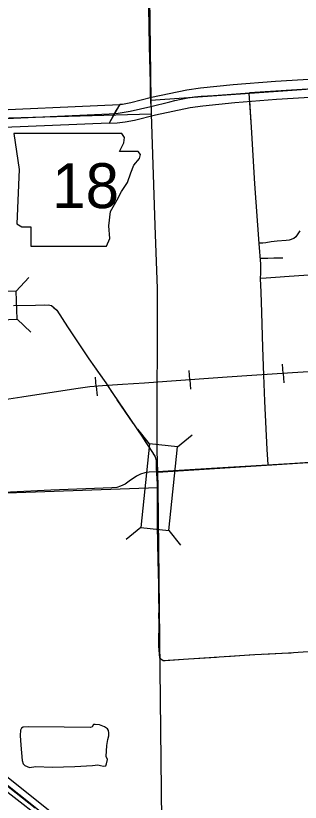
# Model space of a CAD drawing. Extents: x 646058 to 725608, y 1473014 to 1561048.
# Drawn here: x 656968 to 658973, y 1548182 to 1553726 of the extents above; entities that cross this region are included whole.
import ezdxf

# ---------------------------------------------------------------- set-up
doc = ezdxf.new("R2010")
doc.units = 0
doc.layers.add('Default', color=7, linetype='Continuous')

msp = doc.modelspace()

# ---------------------------------------------------------------- linework, layer by layer
at = {"layer": 'Default'}
for p, q in [((656970.4, 1551783.9), (657060, 1551880.9)), ((656978.2, 1551586.1), (657075.2, 1551496.5)), ((658852.6, 1551204.4), (658848.3, 1551270.2)), ((658194.2, 1551158.8), (658189.5, 1551224.6)), ((658852.6, 1551204.4), (658857, 1551138.5)), ((657535.8, 1551113.3), (657530.1, 1551179.1)), ((658194.2, 1551158.8), (658198.9, 1551092.9)), ((657535.8, 1551113.3), (657541.4, 1551047.6)), ((657911.1, 1550709.1), (657828, 1550811.6)), ((658108, 1550688.4), (658210.6, 1550771.5)), ((657849.1, 1550118.3), (657746.5, 1550035.2)), ((658046, 1550097.6), (658129, 1549995.1))]:
    msp.add_line(p, q, dxfattribs=at)
for points in [[(657836.4, 1559731.1), (657852.6, 1558422.3), (657853.7, 1558332.9), (657886.7, 1555776.3), (657888, 1555674.8), (657919.2, 1553129.9), (657922.4, 1553034.6), (657948.9, 1552246.6), (657964.6, 1551804.3), (657962.8, 1550661.1), (657966.7, 1550505.3), (657969.3, 1550400.1), (657996.7, 1547841.2)], [(657882.9, 1555670.5), (657887.5, 1555419.8), (657888.3, 1555210.8), (657889.8, 1554993.3), (657892.9, 1554715.4), (657893.7, 1554428.3), (657896, 1554240.2), (657899.9, 1554036.6), (657904.5, 1553785.1), (657909.2, 1553510.3), (657915.4, 1553253.4), (657916.1, 1553169), (657920.5, 1553086.9)], [(657882.9, 1555670.5), (657887.5, 1555419.8), (657888.3, 1555210.8), (657889.8, 1554993.3), (657892.9, 1554715.4), (657893.7, 1554428.3), (657896, 1554240.2), (657899.9, 1554036.6), (657904.5, 1553785.1), (657909.2, 1553510.3), (657915.4, 1553253.4), (657916.1, 1553169), (657920.5, 1553086.9)], [(660556.3, 1553377.1), (659303, 1553291.8), (658797.5, 1553262.8), (658499.6, 1553239.7), (658270, 1553215.5), (658174.7, 1553201.5), (657924.1, 1553148.8), (657779.1, 1553111.3), (657720, 1553101.1), (657701.2, 1553098.9)], [(657919.2, 1553129.9), (660610.1, 1553321.4)], [(657626.1, 1552968.4), (657682.1, 1552970.7), (657738, 1552977.3), (657805.4, 1552989), (657952.6, 1553027), (658196.6, 1553078.4), (658285.7, 1553091.5), (658510.9, 1553115.2), (658805.9, 1553138.1), (659310.8, 1553167), (660564.1, 1553252.3)], [(658615.3, 1553185.4), (659468.4, 1553238)], [(658615.3, 1553185.4), (659468.4, 1553238)], [(658615.3, 1553185.4), (659468.4, 1553238)], [(658615.3, 1553185.4), (659468.4, 1553238)], [(657920.5, 1553086.9), (658053.9, 1553119.9), (658088.7, 1553128), (658134.8, 1553137.8), (658181.3, 1553146.2), (658228, 1553153), (658274.8, 1553158.3), (658361.6, 1553164.5), (658615.5, 1553181.3)], [(657920.5, 1553086.9), (658053.9, 1553119.9), (658088.7, 1553128), (658134.8, 1553137.8), (658181.3, 1553146.2), (658228, 1553153), (658274.8, 1553158.3), (658361.6, 1553164.5), (658615.5, 1553181.3)], [(657920.5, 1553086.9), (658053.9, 1553119.9), (658088.7, 1553128), (658134.8, 1553137.8), (658181.3, 1553146.2), (658228, 1553153), (658274.8, 1553158.3), (658361.6, 1553164.5), (658615.5, 1553181.3)], [(657920.5, 1553086.9), (658053.9, 1553119.9), (658088.7, 1553128), (658134.8, 1553137.8), (658181.3, 1553146.2), (658228, 1553153), (658274.8, 1553158.3), (658361.6, 1553164.5), (658615.5, 1553181.3)], [(658610.9, 1553181), (658626.1, 1552940.6), (658651.5, 1552540.8), (658681.5, 1552120.8), (658693.1, 1551974.4), (658691.9, 1551912), (658690.7, 1551872.7), (658694.2, 1551776.8), (658698.8, 1551633.6), (658705.8, 1551386.3), (658713.8, 1551193.4), (658721.9, 1551008.5), (658738.1, 1550668.8), (658743.9, 1550562.5)], [(656638.2, 1552990.3), (657627.2, 1553033.1), (657690.5, 1553039.9), (657774.3, 1553053.9), (657920.5, 1553086.9)], [(656638.2, 1552990.3), (657627.2, 1553033.1), (657690.5, 1553039.9), (657774.3, 1553053.9), (657920.5, 1553086.9)], [(656638.2, 1552990.3), (657627.2, 1553033.1), (657690.5, 1553039.9), (657774.3, 1553053.9), (657920.5, 1553086.9)], [(656638.2, 1552990.3), (657627.2, 1553033.1), (657690.5, 1553039.9), (657774.3, 1553053.9), (657920.5, 1553086.9)], [(657701.2, 1553098.9), (657671.2, 1553053.4), (657662, 1553034.2), (657641.1, 1552994.1), (657626.1, 1552968.4)], [(658614.5, 1553123.2), (658626.1, 1552940.6), (658651.5, 1552540.8), (658681.5, 1552120.8), (658693.1, 1551974.4), (658691.9, 1551912), (658690.7, 1551872.7), (658694.2, 1551776.8), (658698.8, 1551633.6), (658705.8, 1551386.3), (658713.8, 1551193.4), (658721.9, 1551008.5), (658738.1, 1550668.8), (658743.9, 1550562.5)], [(655336.8, 1552961.3), (657922.4, 1553034.6)], [(658970.3, 1552209.2), (658942, 1552167.3), (658926.6, 1552156.4), (658895.7, 1552144.8), (658872.6, 1552141.6), (658810.2, 1552136.5), (658767.7, 1552132.6), (658729.8, 1552125.5), (658709.2, 1552121.7), (658682.2, 1552121.7)], [(658970.3, 1552209.2), (658942, 1552167.3), (658926.6, 1552156.4), (658895.7, 1552144.8), (658872.6, 1552141.6), (658810.2, 1552136.5), (658767.7, 1552132.6), (658729.8, 1552125.5), (658709.2, 1552121.7), (658682.2, 1552121.7)], [(658850.1, 1552016.8), (658787.7, 1552017.4), (658744.6, 1552015.5), (658690.6, 1552015.5)], [(658850.1, 1552016.8), (658787.7, 1552017.4), (658744.6, 1552015.5), (658690.6, 1552015.5)], [(659331.8, 1551918.9), (659252.1, 1551914.3), (659123.9, 1551903.9), (659065.5, 1551899.8), (658893.8, 1551886.9), (658799.3, 1551879.9), (658733.7, 1551876), (658693.1, 1551873.4)], [(659331.8, 1551918.9), (659252.1, 1551914.3), (659123.9, 1551903.9), (659065.5, 1551899.8), (658893.8, 1551886.9), (658799.3, 1551879.9), (658733.7, 1551876), (658693.1, 1551873.4)], [(656953.5, 1551682.6), (657106.9, 1551686.7), (657197.7, 1551689.2), (657219.1, 1551683.4), (657257.9, 1551649.6), (657332.9, 1551534.1), (657483.1, 1551308), (657602.7, 1551138.1), (657651.3, 1551062.2), (657856.7, 1550761.9), (657931, 1550647.2), (657950.7, 1550616.7), (657957.3, 1550593.6), (657958.2, 1550536.6), (657964.8, 1550424.4), (657964.8, 1550133.2), (657968.9, 1549886.5), (657973, 1549734.7), (657975.5, 1549433.6), (657973.8, 1549282.6), (657980.4, 1549200.1), (658007.8, 1549181.5), (658652.9, 1549223.3), (658891.1, 1549235.4), (659096.2, 1549249.3)], [(656953.5, 1551682.6), (657106.9, 1551686.7), (657197.7, 1551689.2), (657219.1, 1551683.4), (657257.9, 1551649.6), (657332.9, 1551534.1), (657483.1, 1551308), (657602.7, 1551138.1), (657651.3, 1551062.2), (657856.7, 1550761.9), (657931, 1550647.2), (657950.7, 1550616.7), (657957.3, 1550593.6), (657958.2, 1550536.6), (657964.8, 1550424.4), (657964.8, 1550133.2), (657968.9, 1549886.5), (657973, 1549734.7), (657975.5, 1549433.6), (657973.8, 1549282.6), (657980.4, 1549200.1), (658007.8, 1549181.5), (658652.9, 1549223.3), (658891.1, 1549235.4), (659096.2, 1549249.3)], [(656976.1, 1551683.2), (657106.9, 1551686.7), (657174, 1551688.5)], [(657234.3, 1551670.2), (657257.9, 1551649.6), (657332.9, 1551534.1), (657348.9, 1551510)], [(657385.4, 1551455), (657483.1, 1551308), (657495.5, 1551290.4)], [(659218.5, 1551226.8), (658919.4, 1551208.8), (658632.7, 1551189.9), (658458.5, 1551177.6), (658032.7, 1551147.3), (657875.6, 1551136.9), (657719.4, 1551126.4), (657578.4, 1551117), (657490.4, 1551109.4), (657409, 1551098.1), (657177.2, 1551062.1), (657010.6, 1551037.5), (656855.4, 1551014.8)], [(659218.5, 1551226.8), (658919.4, 1551208.8), (658632.7, 1551189.9), (658458.5, 1551177.6), (658032.7, 1551147.3), (657875.6, 1551136.9), (657719.4, 1551126.4), (657578.4, 1551117), (657490.4, 1551109.4), (657409, 1551098.1), (657177.2, 1551062.1), (657010.6, 1551037.5), (656855.4, 1551014.8)], [(659218.5, 1551226.8), (658919.4, 1551208.8), (658632.7, 1551189.9), (658458.5, 1551177.6), (658032.7, 1551147.3), (657875.6, 1551136.9), (657719.4, 1551126.4), (657578.4, 1551117), (657490.4, 1551109.4), (657409, 1551098.1), (657177.2, 1551062.1), (657010.6, 1551037.5), (656855.4, 1551014.8)], [(657533.4, 1551236.4), (657602.7, 1551138.1), (657644.6, 1551072.6)], [(657681.6, 1551018), (657793.3, 1550854.5)], [(657830.6, 1550800.1), (657856.7, 1550761.9), (657885.4, 1550717.6)], [(657885.4, 1550717.6), (657931, 1550647.2), (657939.2, 1550634.5)], [(660709.3, 1550682.8), (657966.7, 1550505.3)], [(660277.2, 1550658.5), (660030.7, 1550641.6), (659634.3, 1550614.8), (659338.6, 1550596.1), (659146.1, 1550584.7), (658934.9, 1550570.9), (658743.2, 1550558.7)], [(660277.2, 1550658.5), (660030.7, 1550641.6), (659634.3, 1550614.8), (659338.6, 1550596.1), (659146.1, 1550584.7), (658934.9, 1550570.9), (658743.2, 1550558.7)], [(658743.2, 1550558.7), (658348.4, 1550535.1), (658004, 1550513.2), (657909, 1550508.3), (657878.1, 1550504.3), (657846.4, 1550494.5), (657819.6, 1550481.5), (657768.4, 1550445), (657739.2, 1550424.6), (657706.7, 1550409.2), (657679.9, 1550401.9), (657645.8, 1550398.6), (657215.2, 1550380.8), (656930.9, 1550367.8), (656697, 1550356.4), (656567.8, 1550352.3), (656252.6, 1550336.9), (655973.2, 1550325.5), (655625.5, 1550311.7), (655369.3, 1550300.2)], [(658743.2, 1550558.7), (658348.4, 1550535.1), (658004, 1550513.2), (657909, 1550508.3), (657878.1, 1550504.3), (657846.4, 1550494.5), (657819.6, 1550481.5), (657768.4, 1550445), (657739.2, 1550424.6), (657706.7, 1550409.2), (657679.9, 1550401.9), (657645.8, 1550398.6), (657215.2, 1550380.8), (656930.9, 1550367.8), (656697, 1550356.4), (656567.8, 1550352.3), (656252.6, 1550336.9), (655973.2, 1550325.5), (655625.5, 1550311.7), (655440.8, 1550303.4)], [(657957.6, 1550572.8), (657958.2, 1550536.6), (657964.8, 1550424.4), (657964.8, 1550375)], [(655377.8, 1550308.6), (657969.3, 1550400.1)], [(656694.5, 1550355.3), (656711.3, 1549693.9), (656720.5, 1549034.2), (656727.3, 1548650.4), (656732.4, 1548529.1), (656734.6, 1548515.7), (656736.2, 1548502.5), (656739.9, 1548486.4), (656743.4, 1548475), (656749.1, 1548458.2), (656755.6, 1548443.1), (656765, 1548427.9), (656773.1, 1548416.9), (656784.3, 1548404.4), (656795.4, 1548392.6), (656801.4, 1548387), (656926.2, 1548284.7), (657105, 1548142.8)], [(657964.8, 1550309), (657964.8, 1550133.2), (657965.1, 1550111)], [(657966.2, 1550045.1), (657968.9, 1549886.5), (657970, 1549847.1)], [(657971.8, 1549781.1), (657973, 1549734.7), (657974.3, 1549583.1)], [(657974.8, 1549517.1), (657975.5, 1549433.6), (657974.2, 1549319.2)], [(657976.2, 1549253.3), (657980.4, 1549200.1), (658007.8, 1549181.5), (658020.4, 1549182.3)], [(658185, 1549193), (658382.6, 1549205.8)], [(658448.5, 1549210), (658646.1, 1549222.8)], [(658712, 1549226.3), (658891.1, 1549235.4), (658909.7, 1549236.7)], [(658020.4, 1549182.3), (658119.2, 1549188.7)], [(660769.4, 1545325.6), (660738.5, 1545348.4), (660663.9, 1545400), (660351.8, 1545612.7), (660082.4, 1545798.5), (659708.6, 1546052.2), (659626.2, 1546108.4), (659548.6, 1546163.6), (659466.6, 1546224.7), (659349.1, 1546318.2), (659069.3, 1546541.2), (658623.6, 1546894.9), (658241.6, 1547197.9), (657885.8, 1547482.1), (657634.2, 1547680.9), (657263.8, 1547976.9), (656828.4, 1548315.6), (656441.1, 1548622), (656095.5, 1548896.7), (656046.9, 1548935.5)], [(660769.4, 1545325.6), (660738.5, 1545348.4), (660663.9, 1545400), (660351.8, 1545612.7), (660082.4, 1545798.5), (659708.6, 1546052.2), (659626.2, 1546108.4), (659548.6, 1546163.6), (659466.6, 1546224.7), (659349.1, 1546318.2), (659069.3, 1546541.2), (658623.6, 1546894.9), (658241.6, 1547197.9), (657885.8, 1547482.1), (657634.2, 1547680.9), (657263.8, 1547976.9), (656828.4, 1548315.6), (656441.1, 1548622), (656095.5, 1548896.7), (656046.9, 1548935.5)], [(660769.4, 1545325.6), (660738.5, 1545348.4), (660663.9, 1545400), (660351.8, 1545612.7), (660082.4, 1545798.5), (659708.6, 1546052.2), (659626.2, 1546108.4), (659548.6, 1546163.6), (659466.6, 1546224.7), (659349.1, 1546318.2), (659069.3, 1546541.2), (658623.6, 1546894.9), (658241.6, 1547197.9), (657885.8, 1547482.1), (657634.2, 1547680.9), (657263.8, 1547976.9), (656828.4, 1548315.6), (656441.1, 1548622), (656095.5, 1548896.7), (656046.9, 1548935.5)], [(660769.4, 1545325.6), (660738.5, 1545348.4), (660663.9, 1545400), (660351.8, 1545612.7), (660082.4, 1545798.5), (659708.6, 1546052.2), (659626.2, 1546108.4), (659548.6, 1546163.6), (659466.6, 1546224.7), (659349.1, 1546318.2), (659069.3, 1546541.2), (658623.6, 1546894.9), (658241.6, 1547197.9), (657885.8, 1547482.1), (657634.2, 1547680.9), (657263.8, 1547976.9), (656828.4, 1548315.6), (656441.1, 1548622), (656095.5, 1548896.7), (656046.9, 1548935.5)], [(662563.6, 1543949.1), (662434.9, 1544119.8), (662359.3, 1544214.8), (662291.6, 1544286.1), (662230.9, 1544340.6), (662094.9, 1544448), (661877.3, 1544605.1), (661459.5, 1544882.1), (660209, 1545732), (659458.9, 1546263.3), (659227.1, 1546450.9), (656233.5, 1548837.4)], [(656290.3, 1548854.7), (659253.7, 1546484), (659484.6, 1546297.2), (660233.2, 1545766.9), (661483.2, 1544917.4)], [(657496, 1548709.6), (657310.3, 1548712), (657060.9, 1548713.6), (657020.6, 1548712.8), (657008.3, 1548704.3), (657001.3, 1548690.3), (656999, 1548652.4), (657004.4, 1548585.7), (657013.7, 1548475.7), (657019.9, 1548454.1), (657031.5, 1548441.7), (657065.6, 1548428.5), (657110.5, 1548433.9), (657225.9, 1548429.3), (657384.6, 1548434.7), (657508.5, 1548440.9), (657547.3, 1548445.5), (657564.3, 1548440.9), (657586, 1548437), (657602.3, 1548439.3), (657606.9, 1548454.1), (657613.9, 1548483.5), (657606.1, 1548505.2), (657609.2, 1548581.9), (657616.2, 1548624.5), (657623.9, 1548650.8), (657624.7, 1548671.7), (657622.4, 1548687.2), (657613.9, 1548699.6), (657593.7, 1548713.6), (657558.9, 1548728.3), (657527.9, 1548730.6), (657516.3, 1548729.8), (657506.2, 1548715.1), (657496, 1548709.6)], [(657496, 1548709.6), (657310.3, 1548712), (657060.9, 1548713.6), (657020.6, 1548712.8), (657008.3, 1548704.3), (657001.3, 1548690.3), (656999, 1548652.4), (657004.4, 1548585.7), (657013.7, 1548475.7), (657019.9, 1548454.1), (657031.5, 1548441.7), (657065.6, 1548428.5), (657110.5, 1548433.9), (657225.9, 1548429.3), (657384.6, 1548434.7), (657508.5, 1548440.9), (657547.3, 1548445.5), (657564.3, 1548440.9), (657586, 1548437), (657602.3, 1548439.3), (657606.9, 1548454.1), (657613.9, 1548483.5), (657606.1, 1548505.2), (657609.2, 1548581.9), (657616.2, 1548624.5), (657623.9, 1548650.8), (657624.7, 1548671.7), (657622.4, 1548687.2), (657613.9, 1548699.6), (657593.7, 1548713.6), (657558.9, 1548728.3), (657527.9, 1548730.6), (657516.3, 1548729.8), (657506.2, 1548715.1), (657496, 1548709.6)]]:
    msp.add_lwpolyline(points, dxfattribs=at)
for points in [[(656129.7, 1553033.2), (656649.3, 1553052.3), (657701.2, 1553098.9), (657626.1, 1552968.4), (656654.3, 1552927.4), (656133.6, 1552908.3)], [(656955.2, 1552896.7), (656993.3, 1552643), (656976.4, 1552258.1), (657010.2, 1552236.9), (657073.7, 1552236.9), (657073.7, 1552101.6), (657606.6, 1552101.6), (657632, 1552156.6), (657623.5, 1552245.4), (657636.2, 1552346.9), (657682.7, 1552427.2), (657712.3, 1552486.5), (657754.6, 1552549.9), (657780, 1552617.6), (657801.1, 1552672.6), (657839.2, 1552719.1), (657847.7, 1552748.7), (657830.8, 1552769.8), (657699.6, 1552769.8), (657729.2, 1552829), (657733.5, 1552867.1), (657715.9, 1552896.3)], [(656384.7, 1551562.6), (656978.2, 1551586.1), (656970.4, 1551783.9), (656376.9, 1551760.5)], [(657911.1, 1550709.1), (657849.1, 1550118.3), (658046, 1550097.6), (658108, 1550688.4)]]:
    msp.add_lwpolyline(points, close=True, dxfattribs=at)

# ---------------------------------------------------------------- texts
msp.add_text('18', height=316.5, dxfattribs=at).set_placement((657225.1, 1552369.9))

doc.saveas('drawing.dxf')
